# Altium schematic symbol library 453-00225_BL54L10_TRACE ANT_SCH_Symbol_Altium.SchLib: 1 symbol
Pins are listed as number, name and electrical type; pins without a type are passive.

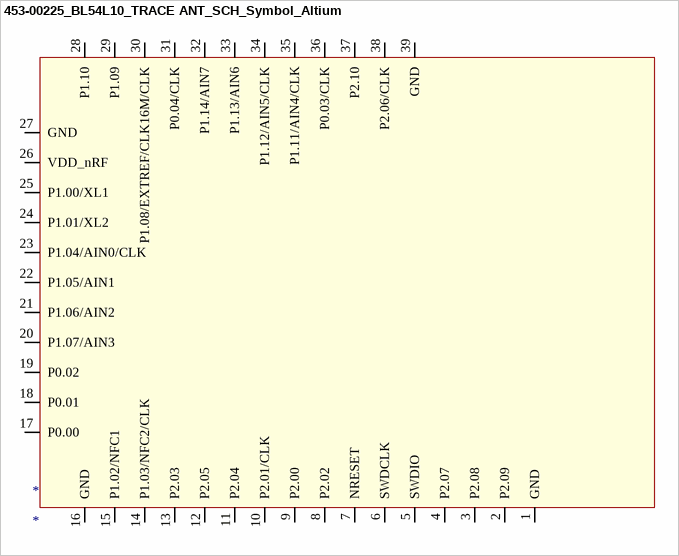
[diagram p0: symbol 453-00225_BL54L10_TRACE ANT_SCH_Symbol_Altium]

## 453-00225_BL54L10_TRACE ANT_SCH_Symbol_Altium
designator *
pins: 1 GND, 2 P2.09, 3 P2.08, 4 P2.07, 5 SWDIO, 6 SWDCLK, 7 NRESET, 8 P2.02, 9 P2.00, 10 P2.01/CLK, 11 P2.04, 12 P2.05, 13 P2.03, 14 P1.03/NFC2/CLK, 15 P1.02/NFC1, 16 GND, 17 P0.00, 18 P0.01, 19 P0.02, 20 P1.07/AIN3, 21 P1.06/AIN2, 22 P1.05/AIN1, 23 P1.04/AIN0/CLK, 24 P1.01/XL2, 25 P1.00/XL1, 26 VDD_nRF, 27 GND, 28 P1.10, 29 P1.09, 30 P1.08/EXTREF/CLK16M/CLK, 31 P0.04/CLK, 32 P1.14/AIN7, 33 P1.13/AIN6, 34 P1.12/AIN5/CLK, 35 P1.11/AIN4/CLK, 36 P0.03/CLK, 37 P2.10, 38 P2.06/CLK, 39 GND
